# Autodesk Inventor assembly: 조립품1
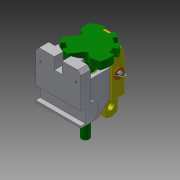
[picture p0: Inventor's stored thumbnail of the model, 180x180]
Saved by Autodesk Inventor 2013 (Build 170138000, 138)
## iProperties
Created: 2016-11
Part Number: 조립품1
Document SubType Name: Assembly
Designer: Administrator
Author: Administrator
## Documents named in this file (8)
- C:\Users\Administrator\Desktop\461107V1009\조립품1.iam
- C:\Users\Administrator\Desktop\461107V1009\본체.ipt
- C:\Users\Administrator\Desktop\461107V1009\부시.ipt
- C:\Users\Administrator\Desktop\461107V1009\분할대.ipt
- C:\Users\Administrator\Desktop\461107V1009\분할축.ipt
- C:\Users\Administrator\Desktop\461107V1009\와셔.ipt
- C:\Users\Administrator\Desktop\461107V1009\원통형핀.ipt
- C:\Users\Administrator\Desktop\461107V1009\클레비스핀.ipt
